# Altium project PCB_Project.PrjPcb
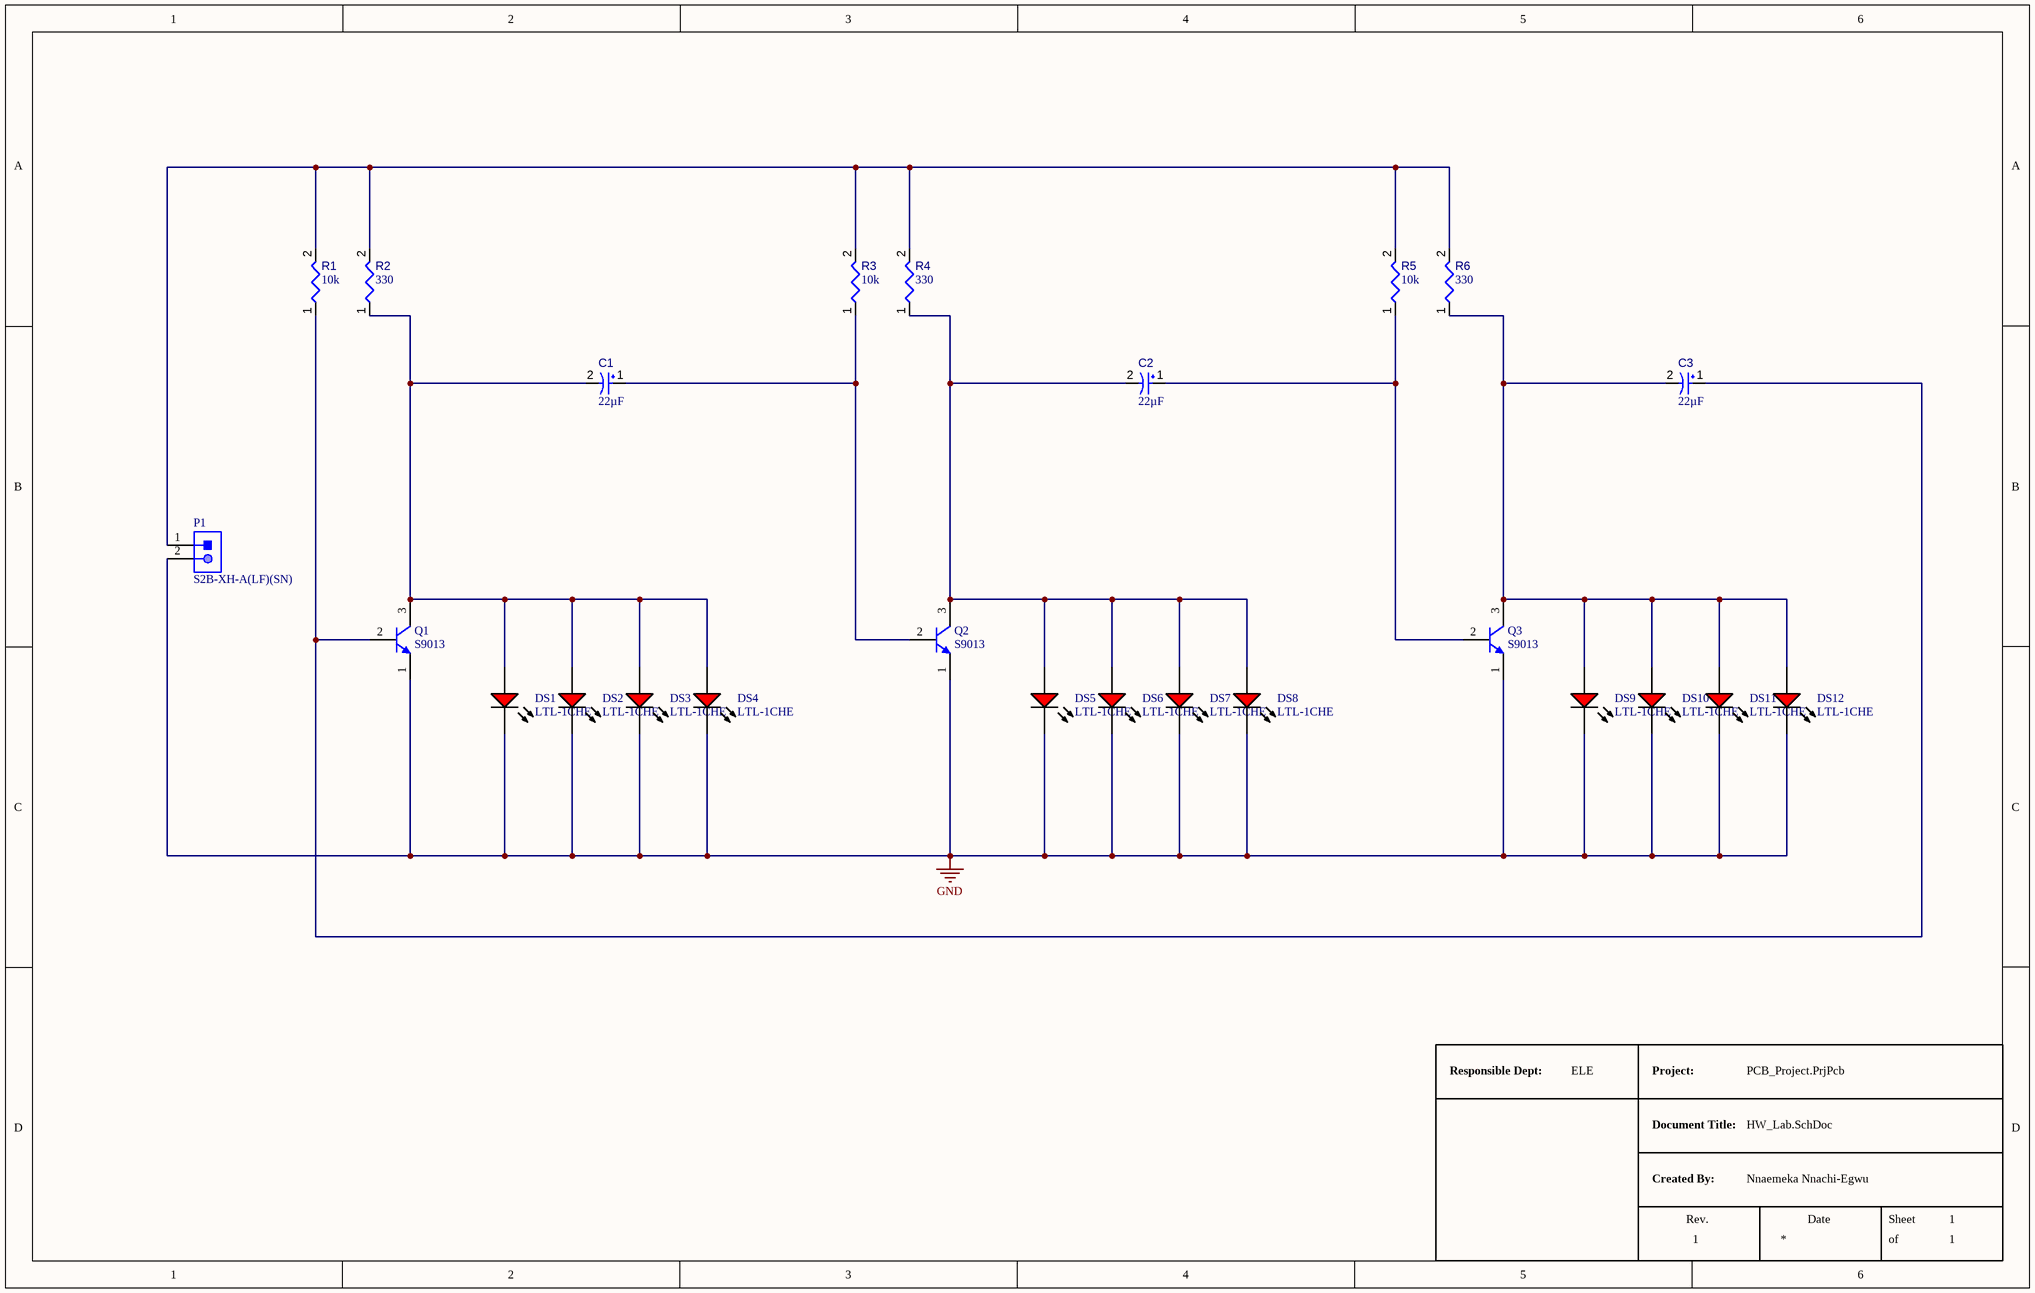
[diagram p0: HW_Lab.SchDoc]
1 sheet, 26 parts. Net scope: global (net labels, ports and power ports of the same name join across sheets).
Board file: PCB1.PcbDoc

## Sheet HW_Lab.SchDoc
size 381 x 241 mm; SheetNumber: 1; SheetTotal: 1

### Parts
*  HSHL_Title_Block  (value not drawn)  (graphical)
C1  value 22µF  [CAPPR55-250-1120X630X1220]  (hidden comment: ECA-2AM220)
C2  value 22µF  [CAPPR55-250-1120X630X1220]  (hidden comment: ECA-2AM220)
C3  value 22µF  [CAPPR55-250-1120X630X1220]  (hidden comment: ECA-2AM220)
DS1  LTL-1CHE  [INDPR60-254-520X380X650]
DS2  LTL-1CHE  [INDPR60-254-520X380X650]
DS3  LTL-1CHE  [INDPR60-254-520X380X650]
DS4  LTL-1CHE  [INDPR60-254-520X380X650]
DS5  LTL-1CHE  [INDPR60-254-520X380X650]
DS6  LTL-1CHE  [INDPR60-254-520X380X650]
DS7  LTL-1CHE  [INDPR60-254-520X380X650]
DS8  LTL-1CHE  [INDPR60-254-520X380X650]
DS9  LTL-1CHE  [INDPR60-254-520X380X650]
DS10  LTL-1CHE  [INDPR60-254-520X380X650]
DS11  LTL-1CHE  [INDPR60-254-520X380X650]
DS12  LTL-1CHE  [INDPR60-254-520X380X650]
P1  S2B-XH-A(LF)(SN)  [JST-S2B-XH-A(LF)(SN)_V]
Q1  S9013  [JSCJ-TO-92-3_V]
Q2  S9013  [JSCJ-TO-92-3_V]
Q3  S9013  [JSCJ-TO-92-3_V]
R1  value 10k  [RESA60-630X240]  (hidden comment: MFR-25FBF52-10K)
R2  value 330  [STA_CF18_STP]  (hidden comment: CF18JT330R)
R3  value 10k  [RESA60-630X240]  (hidden comment: MFR-25FBF52-10K)
R4  value 330  [STA_CF18_STP]  (hidden comment: CF18JT330R)
R5  value 10k  [RESA60-630X240]  (hidden comment: MFR-25FBF52-10K)
R6  value 330  [STA_CF18_STP]  (hidden comment: CF18JT330R)

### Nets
GND: DS1.2(K) DS2.2(K) DS3.2(K) DS4.2(K) DS5.2(K) DS6.2(K) DS7.2(K) DS8.2(K) DS9.2(K) DS10.2(K) DS11.2(K) DS12.2(K) P1.2 Q1.1(E) Q2.1(E) Q3.1(E)
NetC1_1: C1.1 Q2.2(B) R3.1
NetC1_2: C1.2 DS1.1(A) DS2.1(A) DS3.1(A) DS4.1(A) Q1.3(C) R2.1
NetC2_1: C2.1 Q3.2(B) R5.1
NetC2_2: C2.2 DS5.1(A) DS6.1(A) DS7.1(A) DS8.1(A) Q2.3(C) R4.1
NetC3_1: C3.1 Q1.2(B) R1.1
NetC3_2: C3.2 DS9.1(A) DS10.1(A) DS11.1(A) DS12.1(A) Q3.3(C) R6.1
NetP1_1: P1.1 R1.2 R2.2 R3.2 R4.2 R5.2 R6.2

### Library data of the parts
C1-C3 = CMP-001-00035-7: Aluminum Electrolytic Capacitor, 22 uF, +/- 20%, 100 V, -40 to 85 degC, 2-Pin THD, RoHS, Bulk; Manufacturer: Panasonic; Voltage Rating: 100V; Ripple Current: 115mA
DS1-DS12 = CMP-007-00018-2: LED Uni-Color Red, 100 mW, 30 mA, -55 to 100 degC, 2-Pin THD, RoHS, Bulk; Manufacturer: Lite-On; Forward Current: 20mA; Nominal Vf: 2V; Viewing Angle: 60degrees; Luminous Intensity: 12.6mcd; Lens Style: Dome
P1 = CMP-002-00032-2: Male Header, Pitch 2.5 mm, 1 x 2 Position, Height 6.1 mm, Tail Length 3.4 mm, -25 to 85 degC, RoHS, Bulk; Manufacturer: JST
Q1-Q3 = CMP-013-00000-3: Transistor, NPN, 0.1 uA, 150 MHz, 3-Pin TO-92; Manufacturer: Jiangsu Changjiang Electronics Technology
R1 R3 R5 = CMP-009-00047-4: Axial Resistor, 10 KOhm, +/- 1%, 0.25 W, -55 to 155 degC, 2-Pin THD, RoHS, Bulk; Manufacturer: Yageo; Power: 250mW; Voltage Rating: 250V
R2 R4 R6 = CMP-009-00177-2: Fixed Resistor, Carbon Film, 0.125W, 330ohm, 250V, 5% +/-Tol, -400, 0ppm/Cel, Through Hole Mount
